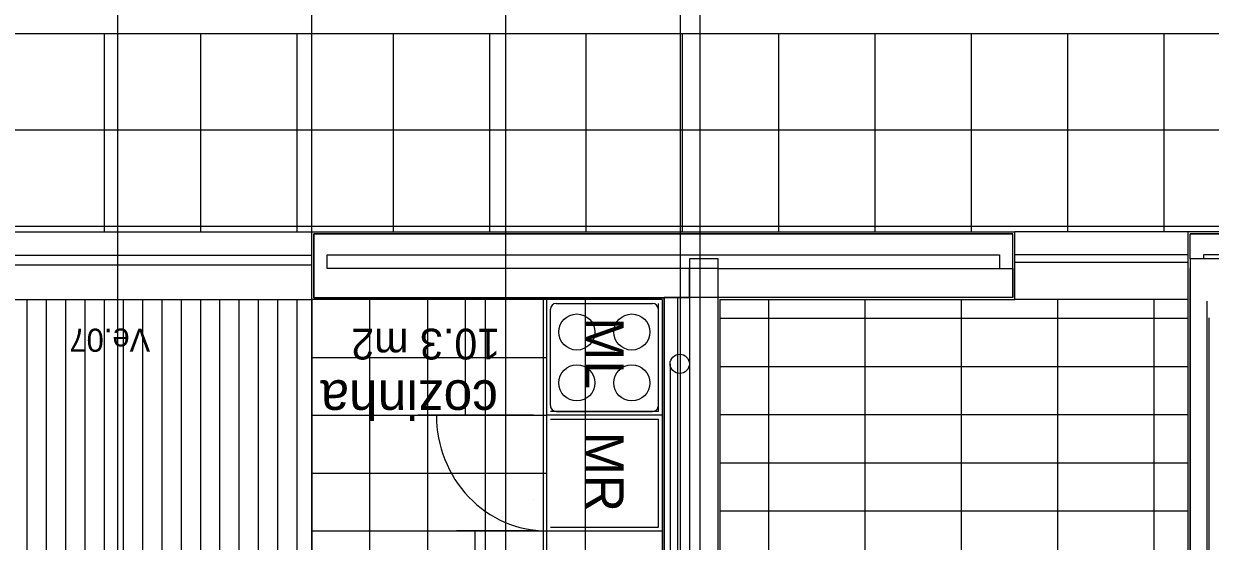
# Model space of a CAD drawing. Extents: x 1248 to 1356, y -443 to -224.
# Drawn here: x 1312.15 to 1318.31, y -233.53 to -230.84 of the extents above; entities that cross this region are included whole.
import ezdxf

# ---------------------------------------------------------------- set-up
doc = ezdxf.new("R2010")
doc.units = 0
for name, color, linetype in [('corte', 7, 'Continuous'), ('estereoctomias', 7, 'Continuous'), ('Level 1', 7, 'Continuous'), ('Level 10', 7, 'Continuous'), ('Level 11', 7, 'Continuous'), ('Level 13', 7, 'Continuous'), ('Level 2', 7, 'Continuous'), ('Level 21', 7, 'Continuous'), ('Level 3', 7, 'Continuous'), ('Level 4', 7, 'Continuous'), ('Level 40', 7, 'Continuous'), ('Level 60', 7, 'Continuous'), ('mob-fixo', 7, 'Continuous'), ('revestimentos', 7, 'Continuous'), ('vermelhos-cont', 7, 'Continuous'), ('vermelhos-tracej', 7, 'Continuous')]:
    doc.layers.add(name, color=color, linetype=linetype)

msp = doc.modelspace()

# ---------------------------------------------------------------- linework, layer by layer
at = {"layer": 'corte'}
for p, q in [((1319.281, -231.934), (1318.2037, -231.934)), ((1318.2037, -232.0639), (1318.2037, -231.934)), ((1317.2144, -232.044), (1317.2144, -232.1143)), ((1319.211, -232.044), (1318.2736, -232.044)), ((1318.2736, -232.044), (1318.2736, -232.0639)), ((1315.7544, -232.1143), (1317.2844, -232.1143)), ((1318.2044, -234.3139), (1318.2044, -232.1143)), ((1315.4744, -232.2659), (1315.4744, -235.1452)), ((1315.5444, -232.264), (1315.5444, -236.7652)), ((1318.3033, -234.124), (1318.3033, -232.3695))]:
    msp.add_line(p, q, dxfattribs=at)
for points in [[(1315.7544, -232.064), (1315.6056, -232.064), (1315.6056, -236.994), (1315.7544, -236.994)], [(1318.2044, -236.5639), (1318.4044, -236.5639), (1318.4044, -232.0639), (1318.2044, -232.0639)], [(1318.2044, -236.5639), (1318.4044, -236.5639), (1318.4044, -232.0639), (1318.2044, -232.0639)]]:
    msp.add_lwpolyline(points, close=True, dxfattribs=at)
at = {"layer": 'estereoctomias'}
for points in [[(1317.2844, -231.934), (1313.6562, -231.934), (1313.6562, -232.2659), (1315.4744, -232.2659), (1315.4744, -232.264), (1315.6056, -232.264), (1315.6056, -232.1143), (1313.7262, -232.1143), (1313.7262, -232.044), (1317.2144, -232.044), (1317.2144, -232.1143), (1317.2844, -232.1143), (1317.2844, -232.044)], [(1317.2844, -231.934), (1313.6562, -231.934), (1313.6562, -232.2659), (1315.4744, -232.2659), (1315.4744, -232.264), (1315.6056, -232.264), (1315.6056, -232.1143), (1313.7262, -232.1143), (1313.7262, -232.044), (1317.2144, -232.044), (1317.2144, -232.1143), (1317.2844, -232.1143), (1317.2844, -232.044)], [(1317.2844, -231.934), (1313.6562, -231.934), (1313.6562, -232.2659), (1315.4744, -232.2659), (1315.4744, -232.264), (1315.6056, -232.264), (1315.6056, -232.1143), (1313.7262, -232.1143), (1313.7262, -232.044), (1317.2144, -232.044), (1317.2144, -232.1143), (1317.2844, -232.1143), (1317.2844, -232.044)], [(1319.281, -232.264), (1319.2653, -232.264), (1319.2653, -232.0639), (1319.211, -232.0639), (1319.211, -232.044), (1318.2736, -232.044), (1318.2736, -232.0639), (1318.2044, -232.0639), (1318.2037, -231.934), (1319.281, -231.934)], [(1317.2844, -232.1143), (1317.2844, -232.264), (1315.7544, -232.264), (1315.7544, -232.1143), (1315.8059, -232.1143)], [(1315.6044, -236.7652), (1315.6044, -236.8352), (1314.7634, -236.8352), (1314.7634, -237.0363), (1314.7334, -237.0363), (1314.7334, -236.8352), (1313.9427, -236.8352), (1313.9427, -237.0363), (1313.8727, -237.0363), (1313.8727, -236.7741), (1313.8727, -236.7652), (1315.4744, -236.7652), (1315.4744, -235.1452), (1313.4359, -235.1452), (1313.4359, -235.0752), (1315.4744, -235.0752), (1315.4744, -232.264), (1315.5444, -232.264), (1315.5444, -236.7652)]]:
    msp.add_lwpolyline(points, close=True, dxfattribs=at)
at = {"layer": 'Level 1'}
for p, q in [((1313.6562, -231.934), (1317.2844, -231.934)), ((1313.6562, -232.2659), (1313.6562, -231.934)), ((1313.6562, -231.934), (1317.2844, -231.934)), ((1313.6562, -231.934), (1317.2844, -231.934)), ((1317.2844, -232.264), (1317.2844, -231.934)), ((1313.7262, -232.044), (1317.2144, -232.044)), ((1313.7262, -232.1143), (1313.7262, -232.044)), ((1313.7262, -232.044), (1317.2144, -232.044)), ((1313.7262, -232.044), (1317.2144, -232.044)), ((1315.7544, -232.1143), (1313.7262, -232.1143)), ((1315.4744, -232.2659), (1313.6562, -232.2659)), ((1317.2844, -232.264), (1315.4744, -232.264))]:
    msp.add_line(p, q, dxfattribs=at)
at = {"layer": 'Level 10'}
for p, q in [((1311.5433, -230.894), (1315.5933, -230.894)), ((1312.5683, -230.894), (1312.5683, -231.924)), ((1313.0683, -230.894), (1313.0683, -231.924)), ((1313.5683, -230.894), (1313.5683, -231.924)), ((1314.0683, -230.894), (1314.0683, -231.924)), ((1314.5683, -230.894), (1314.5683, -231.924)), ((1315.0683, -230.894), (1315.0683, -231.924)), ((1315.5683, -230.894), (1315.5683, -231.924)), ((1315.5933, -230.894), (1318.5759, -230.894)), ((1316.0683, -230.894), (1316.0683, -231.924)), ((1316.5683, -230.894), (1316.5683, -231.924)), ((1317.0683, -230.894), (1317.0683, -231.924)), ((1317.5683, -230.894), (1317.5683, -231.924)), ((1318.0683, -230.894), (1318.0683, -231.924)), ((1311.5433, -231.394), (1315.5933, -231.394)), ((1315.5933, -231.394), (1318.5759, -231.394)), ((1311.4933, -231.894), (1315.5933, -231.894)), ((1315.5933, -231.894), (1318.5759, -231.894)), ((1312.1677, -232.2759), (1312.1677, -236.9259)), ((1312.2677, -232.2759), (1312.2677, -236.9259)), ((1312.3677, -232.2759), (1312.3677, -236.9259)), ((1312.4677, -232.2759), (1312.4677, -236.9259)), ((1312.5677, -232.2759), (1312.5677, -236.9259)), ((1312.6677, -232.2759), (1312.6677, -236.9259)), ((1312.7677, -232.2759), (1312.7677, -236.9259)), ((1312.8677, -232.2759), (1312.8677, -236.9259)), ((1312.9677, -232.2759), (1312.9677, -236.9109)), ((1313.0677, -232.2759), (1313.0677, -236.9259)), ((1313.1677, -232.2759), (1313.1677, -236.9259)), ((1313.2677, -232.2759), (1313.2677, -234.0566)), ((1313.3677, -232.2759), (1313.3677, -234.1388)), ((1313.4677, -232.2759), (1313.4677, -234.4652)), ((1313.5677, -232.2759), (1313.5677, -234.4652)), ((1313.6462, -232.2759), (1313.6462, -234.4652)), ((1313.9462, -232.2759), (1313.9462, -234.4652)), ((1314.2462, -232.2759), (1314.2462, -234.4652)), ((1314.5462, -232.2759), (1314.5462, -234.4652)), ((1314.8462, -232.2759), (1314.8462, -234.4652)), ((1316.0183, -233.624), (1316.0183, -232.2759)), ((1316.5183, -233.624), (1316.5183, -232.274)), ((1317.0183, -234.114), (1317.0183, -232.274)), ((1317.5183, -233.624), (1317.5183, -232.274)), ((1318.0183, -233.624), (1318.0183, -232.274)), ((1318.1944, -232.374), (1315.7644, -232.374)), ((1318.1944, -232.624), (1315.7644, -232.624)), ((1318.1944, -232.874), (1315.7644, -232.874)), ((1318.1944, -233.124), (1315.7644, -233.124)), ((1318.1944, -233.374), (1315.7644, -233.374))]:
    msp.add_line(p, q, dxfattribs=at)
at = {"layer": 'Level 13'}
for p, q in [((1314.8844, -232.826), (1314.8844, -232.326)), ((1314.9144, -232.296), (1315.4144, -232.296)), ((1315.4444, -232.826), (1315.4444, -232.326)), ((1314.9144, -232.856), (1315.4144, -232.856))]:
    msp.add_line(p, q, dxfattribs=at)
for centre in [(1315.0218, -232.4439), (1315.307, -232.4439), (1315.0218, -232.7081), (1315.307, -232.7081)]:
    msp.add_circle(centre, 0.0936, dxfattribs=at)
for centre, start, end in [((1314.9144, -232.326), 90.00005, 180.00003), ((1315.4144, -232.326), 0.00021, 89.99999), ((1314.9144, -232.826), 180.00009, 270.0001), ((1315.4144, -232.826), 269.99985, 0.0002)]:
    msp.add_arc(centre, 0.03, start, end, dxfattribs=at)
at = {"layer": 'Level 2'}
for p, q in [((1311.6312, -231.924), (1313.6462, -231.924)), ((1318.1944, -231.924), (1317.2944, -231.924)), ((1311.6312, -232.0459), (1313.6462, -232.0459)), ((1318.1944, -232.044), (1317.2944, -232.044)), ((1318.1944, -232.084), (1317.2944, -232.084)), ((1311.6312, -232.0959), (1313.6462, -232.0959)), ((1311.6312, -232.2759), (1313.6462, -232.2759)), ((1314.8644, -232.2759), (1314.8644, -234.4652)), ((1318.1944, -232.2759), (1317.2944, -232.2759))]:
    msp.add_line(p, q, dxfattribs=at)
at = {"layer": 'Level 21'}
for p, q in [((1313.6462, -232.5759), (1314.8644, -232.5759)), ((1313.6462, -232.8759), (1314.8644, -232.8759)), ((1313.6462, -233.1759), (1314.8644, -233.1759)), ((1313.6462, -233.4759), (1314.8644, -233.4759))]:
    msp.add_line(p, q, dxfattribs=at)
at = {"layer": 'Level 3'}
msp.add_line((1315.0644, -232.2759), (1315.0644, -234.4652), dxfattribs=at)
msp.add_arc((1314.7955, -233.7556), 0.4426, 89.99999999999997, 90.00000277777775, dxfattribs=at)
at = {"layer": 'Level 4'}
for p, q in [((1314.4429, -232.8759), (1314.4429, -232.2759)), ((1315.4444, -232.8559), (1315.4444, -232.2959)), ((1314.7962, -232.8759), (1314.1962, -232.8759)), ((1315.4644, -232.8759), (1314.8644, -232.8759)), ((1315.4444, -232.8559), (1314.8844, -232.8559)), ((1314.8844, -232.8959), (1315.4444, -232.8959)), ((1315.4444, -233.4559), (1315.4444, -232.8959)), ((1314.7962, -233.4759), (1314.3962, -233.4759)), ((1314.4929, -233.4759), (1314.4929, -233.7072)), ((1314.8644, -233.4759), (1315.4644, -233.4759)), ((1314.8844, -233.4559), (1315.4444, -233.4559))]:
    msp.add_line(p, q, dxfattribs=at)
msp.add_ellipse((1314.8644, -232.8759), major_axis=(0, 0.6), ratio=0.952506, start_param=1.570796, end_param=3.141593, dxfattribs=at)
at = {"layer": 'mob-fixo'}
msp.add_line((1315.5056, -232.609), (1315.5056, -236.8352), dxfattribs=at)
msp.add_circle((1315.5556, -232.609), 0.05, dxfattribs=at)
at = {"layer": 'revestimentos'}
for p, q in [((1313.6462, -232.2759), (1313.6462, -231.924)), ((1313.6462, -231.924), (1317.2944, -231.924)), ((1317.2944, -232.044), (1317.2944, -231.924)), ((1318.3903, -231.924), (1318.1944, -231.924)), ((1318.1944, -234.114), (1318.1944, -231.924)), ((1317.2944, -232.2759), (1317.2944, -232.044)), ((1315.4644, -232.2759), (1313.6462, -232.2759)), ((1315.4644, -232.2759), (1315.4644, -235.0652)), ((1315.7644, -232.2759), (1317.2944, -232.2759)), ((1315.7644, -232.2759), (1315.7644, -237.1163)), ((1318.2933, -234.114), (1318.2933, -232.284))]:
    msp.add_line(p, q, dxfattribs=at)
at = {"layer": 'vermelhos-cont'}
msp.add_line((1315.5589, -250.7923), (1315.5589, -229.6198), dxfattribs=at)
at = {"layer": 'vermelhos-tracej'}
for p, q in [((1312.6387, -235.3039), (1312.6387, -224.3117)), ((1313.6462, -235.3039), (1313.6462, -224.3117)), ((1314.6537, -235.3039), (1314.6537, -224.3117)), ((1315.6612, -234.928), (1315.6612, -224.3117))]:
    msp.add_line(p, q, dxfattribs=at)

# ---------------------------------------------------------------- texts
at = {"layer": 'Level 11'}
for s, p in [('ML', (1315.0644, -232.3681)), ('MR', (1315.0644, -232.9621))]:
    msp.add_text(s, height=0.2, rotation=270, dxfattribs=at).set_placement(p)
at = {"layer": 'Level 40'}
msp.add_text('Ve.07', height=0.12, rotation=180.00001, dxfattribs=at).set_placement((1312.8073, -232.4264))
at = {"layer": 'Level 60'}
for s, height, p in [('10.3 m2', 0.16, (1314.6236, -232.4265)), ('cozinha', 0.2, (1314.6125, -232.6943))]:
    msp.add_text(s, height=height, rotation=180, dxfattribs=at).set_placement(p)

doc.saveas('drawing.dxf')
